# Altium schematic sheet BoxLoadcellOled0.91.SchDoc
size A
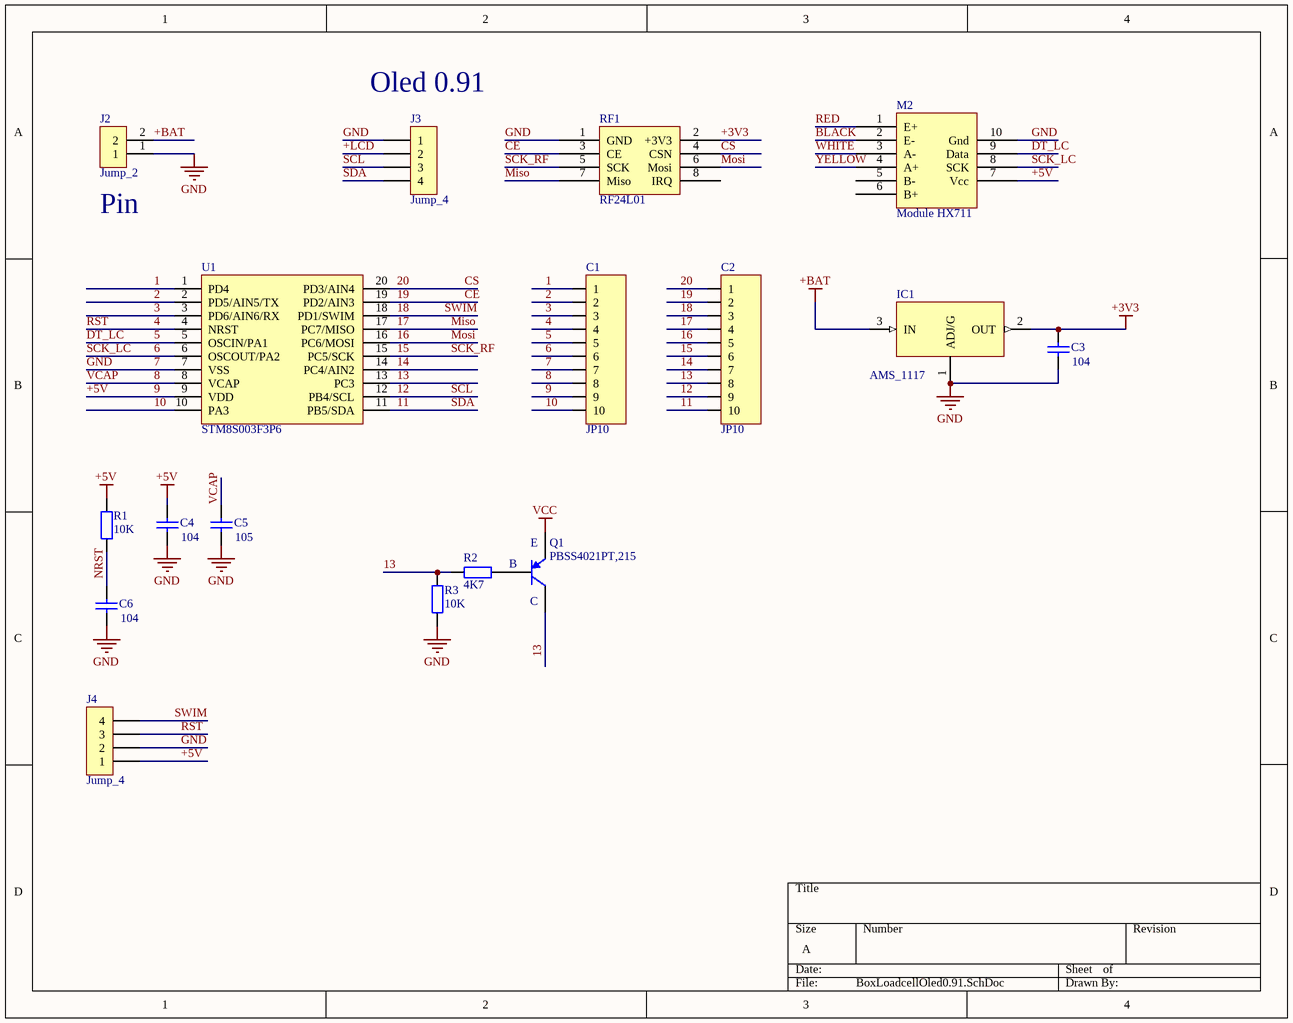
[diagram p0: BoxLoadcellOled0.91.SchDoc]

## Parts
C1  JP10  [JP10-C1T]
C2  JP10  [JP10-C1T]
C3  104  [C0805]
C4  104  [C0805]
C5  105  [C0805]
C6  104  [C0805]
IC1  AMS_1117  [SOT_223_2]
J2  Jump_2  [HT3.96-2P-L-GR]
J3  Jump_4  [Jump_4]
J4  Jump_4  [Jump_4]
M2  Module HX711  [Module HX711]
Q1  PBSS4021PT,215  [SOT23_3]
R1  10K  [RES-0805]
R2  4K7  [RES-0805]
R3  10K  [RES-0805]
RF1  RF24L01  [RF24L01]
U1  STM8S003F3P6  [TSSOP20]

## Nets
7: C1.7 C3.1 C4.1 C5.1 C6.1 IC1.1(ADJ/G) J2.1 J3.1 J4.2 M2.10(Gnd) R3.2 RF1.1(GND) U1.7(VSS)  [also labelled GND]
+3V3: C3.2 IC1.2(OUT) RF1.2(+3V3)
+5V: C1.9 C4.2 J4.1 M2.7(Vcc) R1.2 U1.9(VDD)  [also labelled 9]
+BAT: IC1.3(IN) J2.2
VCC: Q1.2(E)
1: C1.1 U1.1(PD4)
2: C1.2 U1.2(PD5/AIN5/TX)
3: C1.3 U1.3(PD6/AIN6/RX)
4: C1.4 J4.3 U1.4(NRST)  [also labelled RST]
5: C1.5 M2.9(Data) U1.5(OSCIN/PA1)  [also labelled DT_LC]
6: C1.6 M2.8(SCK) U1.6(OSCOUT/PA2)  [also labelled SCK_LC]
8: C1.8 C5.2 U1.8(VCAP)  [also labelled VCAP]
10: C1.10 U1.10(PA3)
11: C2.10 J3.4 U1.11(PB5/SDA)  [also labelled SDA]
12: C2.9 J3.3 U1.12(PB4/SCL)  [also labelled SCL]
13: C2.8 Q1.3(C) R2.2 R3.1 U1.13(PC3)
14: C2.7 U1.14(PC4/AIN2)
15: C2.6 RF1.5(SCK) U1.15(PC5/SCK)  [also labelled SCK_RF]
16: C2.5 RF1.6(Mosi) U1.16(PC6/MOSI)  [also labelled Mosi]
17: C2.4 RF1.7(Miso) U1.17(PC7/MISO)  [also labelled Miso]
18: C2.3 J4.4 U1.18(PD1/SWIM)  [also labelled SWIM]
19: C2.2 RF1.3(CE) U1.19(PD2/AIN3)  [also labelled CE]
20: C2.1 RF1.4(CSN) U1.20(PD3/AIN4)  [also labelled CS]
+LCD: J3.2
BLACK: M2.2(E-)
NRST: C6.2 R1.1
RED: M2.1(E+)
WHITE: M2.3(A-)
YELLOW: M2.4(A+)
NetQ1_1: Q1.1(B) R2.1

Not connected (* = marked no-connect by the designer): M2 5(B-) 6(B+); RF1 8(IRQ)

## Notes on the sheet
- (near J3) Oled 0.91
- (near J2) Pin

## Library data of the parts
C1 C2 = JP10: WR-PHD 2.54 mm Angled Socket Header; Manufacturer: W¨¹rth Elektronik eiSos GmbH; partNo: 613010143121; ComponentLink1 Description: Manufacturer; ComponentLink2 Description: Datasheet; NoPins: 10
C3-C6 = CapSMD: Capacitor; Value: 33p
IC1 = AMS_1117: IC Power
J2 = Jump_2: Jump_2 Pin 2.54
Q1 = PBSS4021PT,215: TRANS PNP 20V 3.5A SOT23; Solder: SMT; CompanyID: VT-00380
R1-R3 = RES: Resistor SMD; Value: 1K
RF1 = RF24L01: Module RF24L01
